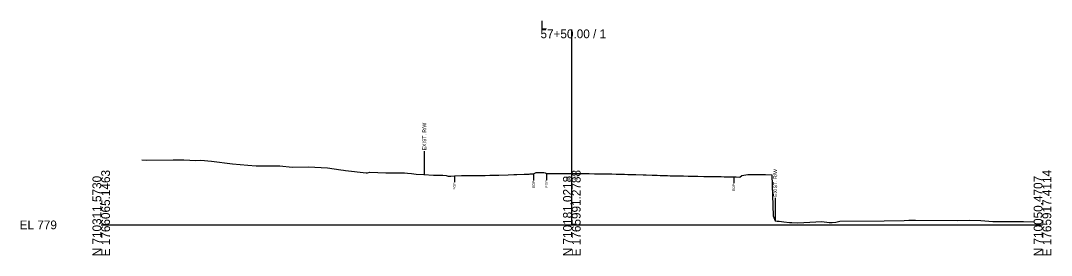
# Model space of a CAD drawing. Extents: x -26 to 5303, y -10 to 9578.
# Drawn here: x 3974.3 to 4302.8, y 7490.3 to 7565 of the extents above; entities that cross this region are included whole.
import ezdxf

# ---------------------------------------------------------------- set-up
doc = ezdxf.new("R2010")
doc.units = 0
for name, color, linetype in [('Exist Cross Section Cell', 7, 'Continuous'), ('Exist XS Ground Line', 7, 'Continuous'), ('Old_Level_10', 7, 'Continuous'), ('Old_Level_3', 7, 'Continuous')]:
    doc.layers.add(name, color=color, linetype=linetype)

msp = doc.modelspace()

# ---------------------------------------------------------------- linework, layer by layer
at = {"layer": 'Exist Cross Section Cell'}
for p, q in [((4150, 7500), (4150, 7562.21)), ((4000, 7500), (4150, 7500)), ((4150, 7500), (4300, 7500))]:
    msp.add_line(p, q, dxfattribs=at)
at = {"layer": 'Exist XS Ground Line'}
msp.add_lwpolyline([(4012.89, 7520.73), (4014.54, 7520.64), (4022.97, 7520.68), (4026.28, 7520.71), (4030.11, 7520.51), (4031.71, 7520.65), (4035.11, 7520.31), (4041.79, 7519.43), (4046.7, 7518.97), (4049.43, 7518.81), (4050.49, 7518.8), (4054.68, 7518.77), (4056.97, 7518.82), (4060.82, 7518.42), (4066.04, 7518.48), (4072.17, 7518.18), (4076.42, 7517.53), (4077.19, 7517.4), (4077.87, 7517.36), (4084.42, 7516.59), (4084.84, 7516.6), (4085.62, 7516.75), (4090.73, 7516.58), (4092.16, 7516.54), (4094.71, 7516.54), (4095.69, 7516.59), (4096.68, 7516.56), (4097.64, 7516.46), (4098.84, 7516.36), (4100.39, 7516.16), (4102.79, 7516.04), (4105.94, 7515.87), (4108.89, 7515.82), (4109.93, 7515.74), (4110.58, 7515.51), (4111.45, 7515.55), (4112.62, 7515.62), (4114.79, 7515.68), (4115.27, 7515.68), (4116.83, 7515.68), (4118.14, 7515.71), (4118.67, 7515.72), (4119.6, 7515.73), (4121.01, 7515.75), (4122.34, 7515.76), (4123.89, 7515.79), (4124.37, 7515.8), (4124.86, 7515.81), (4125.44, 7515.82), (4126.76, 7515.83), (4129.75, 7515.94), (4131.51, 7516.01), (4132.5, 7516.04), (4134.83, 7516.12), (4135.38, 7516.15), (4136.37, 7516.19), (4136.76, 7516.2), (4137.82, 7516.23), (4138.21, 7516.43), (4138.64, 7516.65), (4139.8, 7516.68), (4141.09, 7516.71), (4141.51, 7516.52), (4141.94, 7516.32), (4142.81, 7516.31), (4143.99, 7516.34), (4144.98, 7516.35), (4146.87, 7516.35), (4148.02, 7516.35), (4150.06, 7516.37), (4151.69, 7516.38), (4152.61, 7516.37), (4153.29, 7516.37), (4153.71, 7516.35), (4154.1, 7516.34), (4155.48, 7516.34), (4157.19, 7516.29), (4158.36, 7516.28), (4159.03, 7516.27), (4160.21, 7516.28), (4160.86, 7516.28), (4161.23, 7516.27), (4162.7, 7516.22), (4164.1, 7516.18), (4164.53, 7516.17), (4165.7, 7516.15), (4166.18, 7516.13), (4166.82, 7516.12), (4167.88, 7516.07), (4168.2, 7516.07), (4169.84, 7516.02), (4170.37, 7516.01), (4172.72, 7515.96), (4173.7, 7515.92), (4175.59, 7515.85), (4177.22, 7515.8), (4178.13, 7515.76), (4178.82, 7515.73), (4179.21, 7515.72), (4180.52, 7515.68), (4181.33, 7515.66), (4182.87, 7515.63), (4184.21, 7515.61), (4184.71, 7515.6), (4185.6, 7515.58), (4187.08, 7515.54), (4190.16, 7515.51), (4192.05, 7515.45), (4192.82, 7515.44), (4193.88, 7515.42), (4195.75, 7515.38), (4197.55, 7515.37), (4198.57, 7515.34), (4199.38, 7515.33), (4200.19, 7515.32), (4200.77, 7515.31), (4201.6, 7515.3), (4202.39, 7515.27), (4203.59, 7515.22), (4204.19, 7515.68), (4205.41, 7515.91), (4206.14, 7516.05), (4210.22, 7516.05), (4211.14, 7516.05), (4211.76, 7516.03), (4213.76, 7515.92), (4214.17, 7502.87), (4214.83, 7501.26), (4215.41, 7501.24), (4216.03, 7501.14), (4217.55, 7500.93), (4219.36, 7500.77), (4220.14, 7500.73), (4221.98, 7500.62), (4229.71, 7501.04), (4231.98, 7500.78), (4232.96, 7500.77), (4234.11, 7500.85), (4235.36, 7501.21), (4249.57, 7501.3), (4255.96, 7501.43), (4257.36, 7501.47), (4258.17, 7501.52), (4259.58, 7501.52), (4272.84, 7501.36), (4276.75, 7501.54), (4280.33, 7501.4), (4284.2, 7501.13), (4285.58, 7501.12), (4293.9, 7501.08), (4297.51, 7500.99)], dxfattribs=at)
at = {"layer": 'Old_Level_10'}
for p, q in [((4102.98, 7523.43), (4102.98, 7516.03)), ((4112.62, 7515.62), (4112.62, 7513.57)), ((4137.82, 7516.23), (4137.82, 7514.18)), ((4141.94, 7516.32), (4141.94, 7514.27)), ((4201.6, 7515.3), (4201.6, 7513.25)), ((4214.83, 7508.66), (4214.83, 7501.26))]:
    msp.add_line(p, q, dxfattribs=at)

# ---------------------------------------------------------------- texts
at = {"layer": 'Exist Cross Section Cell'}
for s, p in [('L', (4140, 7562.21)), ('57+50.00 / 1', (4140, 7559.41)), ('EL 779', (3974, 7498.6))]:
    msp.add_text(s, height=2.8, dxfattribs=at).set_placement(p)
for s, p in [('E 1766065.1463', (4002.8, 7490)), ('E 1765991.2788', (4152.8, 7490)), ('E 1765917.4114', (4302.8, 7490)), ('N 710311.5730', (4000, 7490)), ('N 710181.0218', (4150, 7490)), ('N 710050.4707', (4300, 7490))]:
    msp.add_text(s, height=2.8, rotation=90, dxfattribs=at).set_placement(p)
at = {"layer": 'Old_Level_10'}
for s, height, p in [('EXIST. R/W', 1.181, (4103.57, 7523.73)), ('EXIST. R/W', 1.181, (4215.43, 7508.96)), ('EOP', 0.787, (4138.21, 7511.78)), ('EOP', 0.787, (4142.33, 7511.87)), ('EOP', 0.787, (4113.01, 7511.18)), ('EOP', 0.787, (4201.99, 7510.85))]:
    msp.add_text(s, height=height, rotation=90, dxfattribs=at).set_placement(p)
at = {"layer": 'Old_Level_3'}
msp.add_text('795.37', height=1, dxfattribs=at).set_placement((4147.96, 7514.37))

doc.saveas('drawing.dxf')
